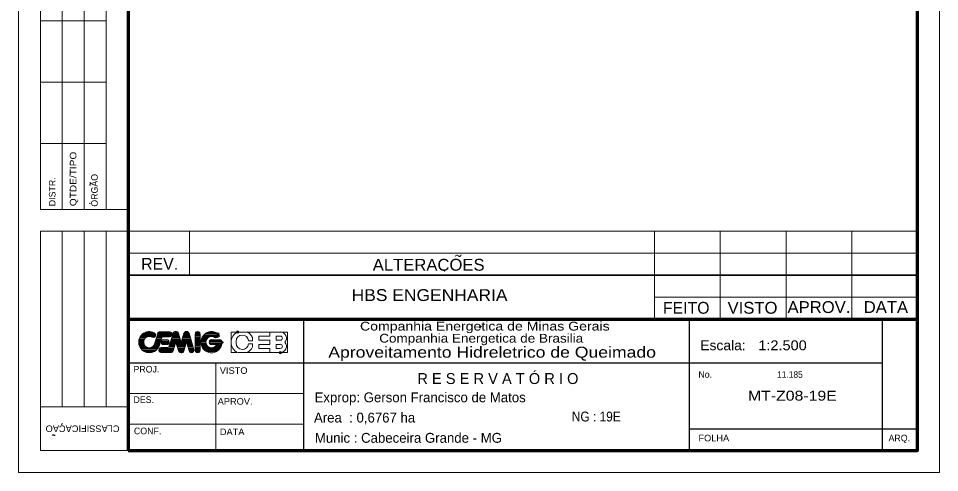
# Model space of a CAD drawing. Extents: x 250991 to 251450, y 8216402 to 8217052.
# Drawn here: x 250991 to 251450.4, y 8216402.4 to 8216628.8 of the extents above; entities that cross this region are included whole.
import ezdxf
from ezdxf.enums import TextEntityAlignment as Align

# ---------------------------------------------------------------- set-up
doc = ezdxf.new("R2010")
doc.units = 0
doc.header["$LTSCALE"] = 2.4
doc.header["$PDMODE"] = 32
doc.header["$PDSIZE"] = 1.2
doc.layers.add('6', color=7, linetype='Continuous', lineweight=13)

msp = doc.modelspace()

# ---------------------------------------------------------------- linework, layer by layer
at = {"layer": '6'}
for p, q in [((251001.92, 8216905.49), (251001.92, 8216533.61)), ((251012.85, 8216905.49), (251012.85, 8216533.61)), ((251023.8, 8216533.61), (251023.8, 8216905.49)), ((251034.72, 8216905.49), (251034.72, 8216533.61)), ((251001.92, 8216627.69), (251034.72, 8216627.69)), ((251001.92, 8216597.06), (251034.72, 8216597.06)), ((251001.92, 8216566.44), (251034.72, 8216566.44)), ((251026.85, 8216536.44), (251026.3, 8216536.66)), ((251045.67, 8216533.61), (251001.92, 8216533.61)), ((251012.85, 8216435.19), (251012.85, 8216522.69)), ((251023.8, 8216435.19), (251023.8, 8216522.69)), ((251034.72, 8216435.19), (251034.72, 8216522.69)), ((251045.67, 8216522.69), (251439.42, 8216522.69)), ((251076.3, 8216500.99), (251076.3, 8216522.69)), ((251308.17, 8216478.94), (251308.17, 8216522.69)), ((251340.97, 8216522.69), (251340.97, 8216478.94)), ((251373.8, 8216478.94), (251373.8, 8216522.69)), ((251406.6, 8216522.69), (251406.6, 8216478.94)), ((251045.67, 8216511.74), (251439.42, 8216511.74)), ((251203.7, 8216503.26), (251203.47, 8216502.61)), ((251308.17, 8216489.86), (251439.42, 8216489.86)), ((251052.1, 8216470.7), (251059.39, 8216470.7)), ((251052.57, 8216471.21), (251059.39, 8216471.21)), ((251053.2, 8216471.71), (251059.1, 8216471.71)), ((251054.17, 8216472.26), (251058.3, 8216472.26)), ((251060.42, 8216471.53), (251058.89, 8216466.58)), ((251060.14, 8216470.7), (251067.42, 8216470.7)), ((251060.31, 8216471.21), (251067.59, 8216471.21)), ((251060.44, 8216471.71), (251067.55, 8216471.71)), ((251060.8, 8216472.26), (251067.2, 8216472.26)), ((251066.37, 8216472.56), (251061.57, 8216472.56)), ((251066.02, 8216465.09), (251068.07, 8216471.74)), ((251067.85, 8216471.04), (251070.97, 8216471.04)), ((251068.01, 8216471.53), (251070.82, 8216471.53)), ((251068.2, 8216472.06), (251070.64, 8216472.06)), ((251068.81, 8216472.59), (251070.01, 8216472.59)), ((251073.26, 8216471.04), (251076.4, 8216471.04)), ((251073.4, 8216471.53), (251076.22, 8216471.53)), ((251073.59, 8216472.06), (251076.05, 8216472.06)), ((251074.22, 8216472.59), (251075.42, 8216472.59)), ((251076.14, 8216471.86), (251078.51, 8216463.81)), ((251079.09, 8216471.53), (251081.57, 8216471.53)), ((251079.09, 8216463.34), (251079.09, 8216471.34)), ((251079.09, 8216470.99), (251081.57, 8216470.99)), ((251079.26, 8216472.03), (251081.4, 8216472.03)), ((251079.82, 8216472.56), (251080.87, 8216472.56)), ((251081.57, 8216471.44), (251081.57, 8216463.34)), ((251083.39, 8216470.94), (251090.69, 8216470.94)), ((251083.95, 8216471.48), (251090.46, 8216471.48)), ((251084.65, 8216471.99), (251089.89, 8216471.99)), ((251085.97, 8216472.53), (251088.57, 8216472.53)), ((251104.97, 8216472.46), (251100.3, 8216472.46)), ((251116.42, 8216472.46), (251121.55, 8216472.46)), ((251050.96, 8216467.58), (251053.42, 8216467.58)), ((251050.96, 8216467.06), (251053.45, 8216467.06)), ((251050.97, 8216468.11), (251053.55, 8216468.11)), ((251050.97, 8216466.56), (251053.55, 8216466.56)), ((251051.1, 8216468.61), (251053.72, 8216468.61)), ((251051.26, 8216469.14), (251054.06, 8216469.14)), ((251051.47, 8216469.65), (251054.6, 8216469.65)), ((251051.75, 8216470.19), (251056.05, 8216470.19)), ((251056.44, 8216470.19), (251059.2, 8216470.19)), ((251058.87, 8216466.56), (251061.47, 8216466.56)), ((251059.05, 8216467.06), (251061.65, 8216467.06)), ((251059.2, 8216467.58), (251061.77, 8216467.58)), ((251059.35, 8216468.11), (251061.95, 8216468.11)), ((251059.52, 8216468.61), (251062.1, 8216468.61)), ((251059.67, 8216469.14), (251062.26, 8216469.14)), ((251059.85, 8216469.65), (251062.42, 8216469.65)), ((251060, 8216470.19), (251066.82, 8216470.19)), ((251061.3, 8216465.86), (251062.44, 8216469.71)), ((251062.14, 8216467.28), (251066.14, 8216467.28)), ((251062.2, 8216467.81), (251066.1, 8216467.81)), ((251062.3, 8216466.74), (251066.01, 8216466.74)), ((251062.55, 8216468.31), (251065.77, 8216468.31)), ((251062.92, 8216466.24), (251065.35, 8216466.24)), ((251062.95, 8216470.09), (251066.37, 8216470.09)), ((251063.35, 8216468.61), (251064.92, 8216468.61)), ((251064.92, 8216466.15), (251063.35, 8216466.15)), ((251066.45, 8216466.36), (251069.15, 8216466.36)), ((251066.59, 8216466.9), (251069.32, 8216466.9)), ((251066.72, 8216467.4), (251069.46, 8216467.4)), ((251066.9, 8216467.91), (251071.92, 8216467.91)), ((251067.05, 8216468.44), (251071.72, 8216468.44)), ((251067.22, 8216468.96), (251071.59, 8216468.96)), ((251067.39, 8216469.48), (251071.47, 8216469.48)), ((251067.55, 8216469.99), (251071.3, 8216469.99)), ((251067.7, 8216470.49), (251071.15, 8216470.49)), ((251069.46, 8216467.4), (251072.06, 8216467.4)), ((251069.64, 8216466.9), (251074.62, 8216466.9)), ((251069.8, 8216466.36), (251074.47, 8216466.36)), ((251072.17, 8216467.4), (251074.76, 8216467.4)), ((251072.32, 8216467.91), (251077.31, 8216467.91)), ((251072.47, 8216468.44), (251077.14, 8216468.44)), ((251072.62, 8216468.96), (251076.97, 8216468.96)), ((251072.8, 8216469.48), (251076.84, 8216469.48)), ((251072.94, 8216469.99), (251076.67, 8216469.99)), ((251073.07, 8216470.49), (251076.55, 8216470.49)), ((251074.82, 8216467.53), (251073.45, 8216462.96)), ((251076.1, 8216463.11), (251074.84, 8216467.56)), ((251074.85, 8216467.4), (251077.45, 8216467.4)), ((251075.05, 8216466.9), (251077.62, 8216466.9)), ((251075.19, 8216466.36), (251077.76, 8216466.36)), ((251079.09, 8216470.48), (251081.57, 8216470.48)), ((251079.09, 8216469.96), (251081.57, 8216469.96)), ((251079.09, 8216469.46), (251081.57, 8216469.46)), ((251079.09, 8216468.94), (251081.57, 8216468.94)), ((251079.09, 8216468.44), (251081.57, 8216468.44)), ((251079.09, 8216467.91), (251081.57, 8216467.91)), ((251079.09, 8216467.4), (251081.57, 8216467.4)), ((251079.09, 8216466.86), (251081.57, 8216466.86)), ((251079.09, 8216466.35), (251081.57, 8216466.35)), ((251082, 8216467.34), (251084.47, 8216467.34)), ((251082.01, 8216467.84), (251084.52, 8216467.84)), ((251082.05, 8216466.81), (251084.52, 8216466.81)), ((251082.09, 8216468.36), (251084.65, 8216468.36)), ((251082.1, 8216466.31), (251084.7, 8216466.31)), ((251082.22, 8216468.9), (251084.89, 8216468.9)), ((251082.42, 8216469.4), (251085.34, 8216469.4)), ((251082.64, 8216469.91), (251086.09, 8216469.91)), ((251082.95, 8216470.46), (251090.64, 8216470.46)), ((251086.01, 8216467.34), (251092.55, 8216467.34)), ((251086.12, 8216467.84), (251092.46, 8216467.84)), ((251086.2, 8216466.81), (251092.51, 8216466.81)), ((251086.51, 8216468.36), (251092.07, 8216468.36)), ((251086.7, 8216466.31), (251092.45, 8216466.31)), ((251091.37, 8216468.61), (251087.26, 8216468.61)), ((251087.26, 8216466.15), (251089.77, 8216466.15)), ((251088.46, 8216469.91), (251090.34, 8216469.91)), ((251099.55, 8216467.86), (251099.55, 8216466.84)), ((251105.7, 8216466.56), (251107.72, 8216466.56)), ((251107.72, 8216464.99), (251107.72, 8216466.56)), ((251121.55, 8216470.41), (251119.5, 8216470.41)), ((251121.55, 8216466.31), (251119.5, 8216466.31)), ((251051.14, 8216466.03), (251053.8, 8216466.03)), ((251051.3, 8216465.53), (251054.17, 8216465.53)), ((251051.5, 8216465.01), (251054.75, 8216465.01)), ((251051.84, 8216464.49), (251060.64, 8216464.49)), ((251052.2, 8216463.99), (251060.22, 8216463.99)), ((251052.7, 8216463.45), (251059.72, 8216463.45)), ((251053.4, 8216462.96), (251059.05, 8216462.96)), ((251054.45, 8216462.44), (251058, 8216462.44)), ((251057.65, 8216465.01), (251060.92, 8216465.01)), ((251058.31, 8216465.53), (251061.17, 8216465.53)), ((251058.67, 8216466.03), (251061.34, 8216466.03)), ((251061, 8216463.28), (251068.22, 8216463.28)), ((251061.05, 8216463.81), (251068.39, 8216463.81)), ((251061.21, 8216462.78), (251068.02, 8216462.78)), ((251061.32, 8216464.31), (251068.57, 8216464.31)), ((251062.01, 8216462.21), (251067.22, 8216462.21)), ((251062.22, 8216464.69), (251065.51, 8216464.69)), ((251066.97, 8216462.21), (251062.22, 8216462.21)), ((251065.89, 8216464.84), (251068.69, 8216464.84)), ((251066.12, 8216465.34), (251068.85, 8216465.34)), ((251066.26, 8216465.86), (251069.02, 8216465.86)), ((251069.94, 8216465.86), (251074.32, 8216465.86)), ((251070.1, 8216465.34), (251074.15, 8216465.34)), ((251070.25, 8216464.84), (251074.01, 8216464.84)), ((251070.39, 8216464.31), (251073.85, 8216464.31)), ((251070.55, 8216463.81), (251073.71, 8216463.81)), ((251070.71, 8216463.28), (251073.55, 8216463.28)), ((251070.85, 8216462.78), (251073.37, 8216462.78)), ((251071.42, 8216462.21), (251072.81, 8216462.21)), ((251075.32, 8216465.86), (251077.89, 8216465.86)), ((251075.45, 8216465.34), (251078.06, 8216465.34)), ((251075.62, 8216464.84), (251078.2, 8216464.84)), ((251075.76, 8216464.31), (251078.35, 8216464.31)), ((251075.94, 8216463.81), (251078.51, 8216463.81)), ((251076.07, 8216463.28), (251078.57, 8216463.28)), ((251076.26, 8216462.78), (251078.42, 8216462.78)), ((251076.8, 8216462.21), (251077.85, 8216462.21)), ((251079.09, 8216465.84), (251081.57, 8216465.84)), ((251079.09, 8216465.34), (251081.57, 8216465.34)), ((251079.09, 8216464.79), (251081.57, 8216464.79)), ((251079.09, 8216464.28), (251081.57, 8216464.28)), ((251079.09, 8216463.78), (251081.57, 8216463.78)), ((251079.09, 8216463.24), (251081.57, 8216463.24)), ((251079.3, 8216462.71), (251081.4, 8216462.71)), ((251079.87, 8216462.21), (251080.82, 8216462.21)), ((251082.26, 8216465.78), (251085, 8216465.78)), ((251082.45, 8216465.24), (251085.47, 8216465.24)), ((251082.72, 8216464.74), (251086.39, 8216464.74)), ((251083.07, 8216464.23), (251091.47, 8216464.23)), ((251083.47, 8216463.69), (251091.07, 8216463.69)), ((251084.09, 8216463.19), (251090.46, 8216463.19)), ((251084.89, 8216462.66), (251089.64, 8216462.66)), ((251086.6, 8216462.15), (251087.92, 8216462.15)), ((251088.17, 8216464.74), (251091.82, 8216464.74)), ((251089.1, 8216465.24), (251092.1, 8216465.24)), ((251089.56, 8216465.78), (251092.3, 8216465.78)), ((251104.97, 8216462.21), (251100.62, 8216462.21)), ((251116.42, 8216462.21), (251121.55, 8216462.21)), ((251089.42, 8216457.06), (251089.42, 8216413.31)), ((251045.67, 8216441.74), (251133.17, 8216441.74)), ((251001.92, 8216435.19), (251045.67, 8216435.19)), ((251012.6, 8216426.11), (251012.82, 8216426.99)), ((251045.67, 8216426.44), (251133.17, 8216426.44))]:
    msp.add_line(p, q, dxfattribs=at)
at = {"layer": '6', "lineweight": 35}
msp.add_line((251045.67, 8216500.81), (251439.42, 8216500.81), dxfattribs=at)
at = {"layer": '6', "lineweight": 70}
msp.add_line((251045.67, 8216478.94), (251439.42, 8216478.94), dxfattribs=at)
at = {"layer": '6', "lineweight": 25}
for p, q in [((251133.17, 8216478.94), (251133.17, 8216413.31)), ((251221.07, 8216474.39), (251221.95, 8216475.49)), ((251325.67, 8216413.31), (251325.67, 8216478.94)), ((251421.92, 8216413.31), (251421.92, 8216478.94)), ((251045.67, 8216457.06), (251421.92, 8216457.06)), ((251325.67, 8216424.24), (251439.42, 8216424.24))]:
    msp.add_line(p, q, dxfattribs=at)
at = {"layer": '6'}
msp.add_lwpolyline([(250990.97, 8216402.36), (251450.35, 8216402.36), (251450.35, 8217052.06), (250990.97, 8217052.06)], close=True, dxfattribs=at)
at = {"layer": '6', "lineweight": 70}
msp.add_lwpolyline([(251045.67, 8216413.31), (251439.42, 8216413.31), (251439.42, 8217041.11), (251045.67, 8217041.11)], close=True, dxfattribs=at)
at = {"layer": '6'}
for points in [[(251045.67, 8216413.31), (251001.92, 8216413.31), (251001.92, 8216522.69), (251045.67, 8216522.69)], [(251066.37, 8216472.56), (251061.57, 8216472.56), (251066.37, 8216472.56)], [(251070.8, 8216471.78), (251072.1, 8216467.24), (251073.47, 8216471.81)], [(251100.3, 8216472.46), (251097, 8216472.46), (251097, 8216467.34)], [(251104.97, 8216472.46), (251116.42, 8216472.46), (251116.42, 8216470.41), (251110.82, 8216470.41), (251110.82, 8216468.36), (251116.42, 8216468.36), (251116.42, 8216466.31), (251110.82, 8216466.31), (251110.82, 8216464.29), (251116.42, 8216464.29), (251116.42, 8216462.21), (251104.97, 8216462.21)], [(251121.55, 8216462.21), (251125.15, 8216462.21), (251125.15, 8216472.46), (251121.55, 8216472.46)], [(251063.35, 8216468.61), (251064.92, 8216468.61), (251063.35, 8216468.61)], [(251070.76, 8216463.09), (251069.46, 8216467.4), (251068.2, 8216463.15)], [(251097, 8216467.34), (251097, 8216462.21), (251100.3, 8216462.21), (251100.27, 8216462.21)], [(251105.7, 8216468.11), (251107.72, 8216468.11), (251107.72, 8216469.69)], [(251119.5, 8216470.41), (251119.5, 8216468.36), (251121.55, 8216468.36)], [(251119.5, 8216466.31), (251119.5, 8216464.29), (251121.55, 8216464.29)]]:
    msp.add_lwpolyline(points, dxfattribs=at)
for centre, radius, start, end in [((251056.217, 8216467.407), 5.279, 60.51986, 343.11893), ((251058.173, 8216470.937), 1.242, 235.21396, 65.35832), ((251061.62, 8216471.34), 1.242, 87.13759, 170.18874), ((251066.34, 8216471.34), 1.242, 265.44623, 91.43209), ((251069.258, 8216471.444), 1.242, 82.81573, 166.414), ((251069.569, 8216471.444), 1.242, 14.03624, 98.40891), ((251074.64, 8216471.444), 1.242, 81.3986, 168.03793), ((251074.951, 8216471.444), 1.242, 10.56101, 98.60138), ((251080.333, 8216471.444), 1.242, 355.4978, 183.81406), ((251080.333, 8216471.444), 1.242, 355.4978, 183.81406), ((251080.333, 8216471.444), 1.242, 355.49781, 183.81406), ((251087.267, 8216467.407), 5.279, 56.684, 0.67404), ((251089.441, 8216470.802), 1.242, 231.58194, 58.45584), ((251089.441, 8216470.802), 1.242, 231.58194, 58.45584), ((251089.441, 8216470.802), 1.242, 231.58194, 58.45584), ((251102.624, 8216467.354), 5.631, 114.61998, 180), ((251102.624, 8216467.866), 3.071, 4.78019, 180), ((251102.624, 8216467.354), 5.631, 24.61998, 65.38002), ((251121.563, 8216469.402), 3.071, 318.18969, 90), ((251056.217, 8216467.407), 2.795, 61.72795, 343.03727), ((251063.359, 8216467.407), 1.242, 84.2894, 274.28914), ((251062.922, 8216469.581), 0.517, 89.99996, 162.02084), ((251064.911, 8216467.407), 1.242, 265.04973, 90.95483), ((251087.267, 8216467.407), 2.795, 57.02091, 333.72578), ((251087.267, 8216467.407), 1.242, 85.19651, 273.81407), ((251091.304, 8216467.407), 1.242, 354.20078, 95.23747), ((251102.624, 8216467.354), 5.631, 180, 245.38002), ((251102.624, 8216466.842), 3.071, 180, 355.21981), ((251121.563, 8216469.402), 1.024, 270, 90), ((251121.563, 8216465.307), 3.071, 270, 41.81031), ((251121.563, 8216465.307), 1.024, 270, 90), ((251062.22, 8216463.474), 1.242, 89.52254, 273.57633), ((251062.22, 8216463.474), 1.242, 89.52254, 273.57633), ((251062.22, 8216463.474), 1.242, 89.52254, 273.57633), ((251065.529, 8216465.234), 0.517, 269.99998, 343.09819), ((251066.981, 8216463.474), 1.242, 264.94274, 348.40781), ((251071.949, 8216463.371), 1.242, 192.99461, 278.60138), ((251072.26, 8216463.371), 1.242, 261.07601, 342.47442), ((251077.331, 8216463.371), 1.242, 190.56101, 24.36245), ((251080.333, 8216463.371), 1.242, 179.05304, 4.18491), ((251102.624, 8216467.354), 5.631, 294.61998, 335.38002)]:
    msp.add_arc(centre, radius, start, end, dxfattribs=at)
for points in [[(251026.85, 8216545.64), (251026.57, 8216545.84), (251026.8, 8216546.39), (251027, 8216546.69), (251026.52, 8216547.06)], [(251208.7, 8216510.11), (251209.25, 8216510.66), (251209.95, 8216510.84), (251210.5, 8216510.29), (251210.77, 8216510.16), (251211.27, 8216510.29), (251211.8, 8216510.94)], [(251009.27, 8216421.16), (251009.05, 8216420.89), (251008.5, 8216421.09), (251008.22, 8216421.31), (251007.85, 8216420.84)]]:
    msp.add_spline(points, degree=3, dxfattribs=at)
for p in [(251090.46, 8216471.48), (251090.64, 8216470.46), (251100.3, 8216472.46), (251069.46, 8216467.4), (251092.55, 8216467.34), (251121.55, 8216462.21)]:
    msp.add_point(p, dxfattribs=at)

# ---------------------------------------------------------------- texts
for s, rotation, width, p in [('QTDE/TIPO', 90, 1.15, (251019.88, 8216535.19)), ('CLASSIFICACAO', 180, 1.05, (251041.4, 8216425.87))]:
    msp.add_text(s, height=3.281, rotation=rotation, dxfattribs=dict(at, width=width)).set_placement(p)
for s, p in [('DISTR.', (251009.45, 8216535.19)), ('ORGAO', (251030.53, 8216534.97))]:
    msp.add_text(s, height=3.281, rotation=90, dxfattribs=at).set_placement(p)
for s, height, p in [('REV.', 5.906, (251052.18, 8216503.49)), ('FEITO', 5.906, (251312.38, 8216481.57)), ('PROJ.', 3.281, (251048.35, 8216452.27)), ('No.', 3.281, (251330.08, 8216449.62)), ('DES.', 3.281, (251048.35, 8216437.09)), ('Exprop: Gerson Francisco de Matos', 4.92, (251138.66, 8216437.42)), ('Area  : 0,6767 ha', 4.92, (251138.36, 8216427.32)), ('CONF.', 3.281, (251048.58, 8216421.47)), ('Munic : Cabeceira Grande - MG', 4.925, (251138.79, 8216417.22)), ('ARQ.', 3.281, (251424.9, 8216417.94))]:
    msp.add_text(s, height=height, dxfattribs=at).set_placement(p)
for s, height, width, p in [('ALTERACOES', 5.906, 1.05, (251167.68, 8216503.04)), ('HBS ENGENHARIA', 5.906, 1.1, (251157.15, 8216487.92)), ('VISTO', 5.906, 1.05, (251344.63, 8216481.59)), ('APROV.', 5.906, 1.05, (251374.53, 8216481.94)), ('DATA', 5.906, 1.05, (251412.53, 8216481.94)), ('Companhia Energetica de Minas Gerais', 4.375, 1.2, (251161.33, 8216473.19)), ('Companhia Energetica de Brasilia', 4.375, 1.15, (251170.9, 8216467.17)), ('VISTO', 3.281, 1.05, (251091.4, 8216451.59)), ('11.185', 3.281, 0.95, (251369.35, 8216449.62)), ('APROV.', 3.281, 1.05, (251090.33, 8216436.22)), ('DATA', 3.281, 1.05, (251091.4, 8216421.04)), ('FOLHA', 3.281, 1.05, (251330.08, 8216417.94))]:
    msp.add_text(s, height=height, dxfattribs=dict(at, width=width)).set_placement(p)
for s, height, width, p in [('Escala: ', 4.922, 1.05, (251343.315, 8216463.37)), ('1:2.500', 4.92, 1.1, (251372.03, 8216463.37)), ('Aproveitamento Hidreletrico de Queimado', 5.469, 1.2, (251227.21, 8216459.67)), ('MT-Z08-19E', 4.92, 1.2, (251376.94, 8216438.24)), ('NG : 19E', 4.92, 0.9, (251279.14, 8216427.84))]:
    msp.add_text(s, height=height, dxfattribs=dict(at, width=width)).set_placement(p, align=Align.CENTER)
msp.add_text('R E S E R V A T Ó R I O', height=5.462, dxfattribs=at).set_placement((251230.075, 8216446.52), align=Align.CENTER)

doc.saveas('drawing.dxf')
